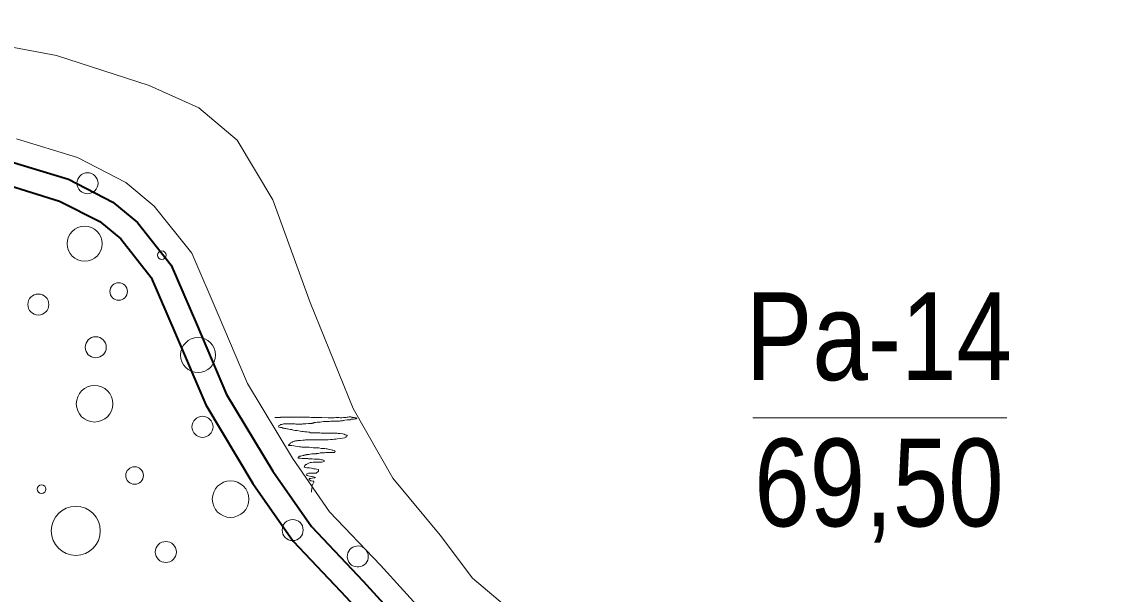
# Model space of a CAD drawing. Extents: x 640104 to 640970, y 6442278 to 6442689.
# Drawn here: x 640619.99 to 640656.92, y 6442622.5 to 6442642.09 of the extents above; entities that cross this region are included whole.
import ezdxf
from ezdxf.enums import TextEntityAlignment as Align

# ---------------------------------------------------------------- set-up
doc = ezdxf.new("R2010")
doc.units = 0
doc.header["$LTSCALE"] = 1.2
doc.linetypes.add('MEDIUM_DASHED', pattern=[4.5, 3, -1.5])
for name, color, linetype, lineweight in [('31', 7, 'Continuous', 13), ('32', 7, 'Continuous', 25), ('35', 7, 'Continuous', 35), ('40', 7, 'Continuous', 13), ('41', 7, 'Continuous', 13)]:
    doc.layers.add(name, color=color, linetype=linetype, lineweight=lineweight)

msp = doc.modelspace()

# ---------------------------------------------------------------- linework, layer by layer
at = {"layer": '31'}
for points in [[(640614.97, 6442642.09), (640621.18, 6442640.93), (640624.35, 6442639.91), (640626.05, 6442639.14), (640627.36, 6442638.03), (640628.58, 6442635.99), (640629.86, 6442632.49), (640631.33, 6442628.86), (640632.69, 6442626.48), (640634.3, 6442624.53), (640635.41, 6442623.06), (640637.17, 6442621.58), (640640.5, 6442618.88), (640642.64, 6442617.25), (640645.69, 6442615.13), (640647.73, 6442614.4), (640649.77, 6442613.94), (640651.6, 6442612.37), (640655.67, 6442609.41), (640658.72, 6442607.17)], [(640619.82, 6442638.08), (640621.9, 6442637.44), (640623.55, 6442636.59), (640624.53, 6442635.78), (640625.81, 6442634.17), (640626.71, 6442632.07), (640627.72, 6442629.71), (640629.25, 6442627.16), (640630.52, 6442625.33), (640632.26, 6442623.5), (640635.41, 6442620.04), (640639.01, 6442616.68), (640643.82, 6442612.84), (640649.81, 6442608.89), (640651.34, 6442607.83), (640657.57, 6442604.59)]]:
    msp.add_lwpolyline(points, dxfattribs=at)
at = {"layer": '32', "lineweight": 13}
msp.add_line((640645, 6442628.54), (640653.68, 6442628.54), dxfattribs=at)
at = {"layer": '35', "lineweight": 40}
msp.add_lwpolyline([(640619.6, 6442637.31), (640621.6, 6442636.7), (640623.11, 6442635.92), (640623.96, 6442635.22), (640625.11, 6442633.76), (640625.97, 6442631.76), (640627, 6442629.34), (640628.58, 6442626.72), (640629.9, 6442624.82), (640631.67, 6442622.96), (640634.84, 6442619.48), (640638.49, 6442616.08), (640643.35, 6442612.19), (640649.36, 6442608.23), (640650.93, 6442607.14), (640657.23, 6442603.87)], dxfattribs=at)
at = {"layer": '35', "linetype": 'MEDIUM_DASHED'}
msp.add_lwpolyline([(640619.39, 6442636.54), (640621.29, 6442635.95), (640622.67, 6442635.25), (640623.38, 6442634.66), (640624.42, 6442633.34), (640625.24, 6442631.44), (640626.29, 6442628.98), (640627.9, 6442626.29), (640629.28, 6442624.32), (640631.09, 6442622.41), (640634.27, 6442618.92), (640637.96, 6442615.47), (640642.88, 6442611.54), (640648.92, 6442607.56), (640650.51, 6442606.45), (640656.89, 6442603.14), (640661.89, 6442601.05)], dxfattribs=at)
at = {"layer": '40'}
for points in [[(640628.65, 6442628.55), (640628.69, 6442628.55), (640628.76, 6442628.55), (640628.84, 6442628.55), (640628.85, 6442628.56), (640628.92, 6442628.56), (640629.03, 6442628.56), (640629.24, 6442628.56), (640629.36, 6442628.56), (640629.39, 6442628.56), (640629.41, 6442628.56), (640629.46, 6442628.56), (640629.52, 6442628.56), (640629.59, 6442628.56), (640629.64, 6442628.56), (640629.68, 6442628.56), (640629.74, 6442628.56), (640629.79, 6442628.56), (640629.84, 6442628.56), (640629.89, 6442628.55), (640629.92, 6442628.55), (640629.97, 6442628.55), (640630.04, 6442628.55), (640630.26, 6442628.55), (640630.47, 6442628.54), (640630.53, 6442628.54), (640630.57, 6442628.54), (640630.6, 6442628.54), (640630.63, 6442628.54), (640630.68, 6442628.54), (640630.74, 6442628.55), (640630.77, 6442628.55), (640630.8, 6442628.55), (640630.81, 6442628.55), (640630.84, 6442628.55), (640630.88, 6442628.54), (640630.91, 6442628.54), (640630.94, 6442628.54), (640631, 6442628.55), (640631.04, 6442628.55), (640631.09, 6442628.55), (640631.12, 6442628.56), (640631.16, 6442628.56), (640631.19, 6442628.57), (640631.22, 6442628.57), (640631.25, 6442628.57), (640631.28, 6442628.56), (640631.3, 6442628.55), (640631.33, 6442628.55), (640631.36, 6442628.55)], [(640629.68, 6442628.34), (640629.65, 6442628.33), (640629.61, 6442628.33), (640629.59, 6442628.32), (640629.56, 6442628.32), (640629.54, 6442628.32), (640629.51, 6442628.32), (640629.48, 6442628.32), (640629.44, 6442628.32), (640629.4, 6442628.32), (640629.37, 6442628.32), (640629.33, 6442628.33), (640629.31, 6442628.33), (640629.28, 6442628.33), (640629.26, 6442628.33), (640629.23, 6442628.33), (640629.2, 6442628.33), (640629.15, 6442628.33), (640629.12, 6442628.33), (640629.1, 6442628.33), (640629.06, 6442628.33), (640629.04, 6442628.33), (640629, 6442628.33), (640628.98, 6442628.33), (640628.95, 6442628.33), (640628.92, 6442628.32), (640628.89, 6442628.31), (640628.86, 6442628.31), (640628.84, 6442628.3), (640628.82, 6442628.29), (640628.8, 6442628.28), (640628.79, 6442628.27), (640628.78, 6442628.24), (640628.79, 6442628.22), (640628.85, 6442628.21), (640628.89, 6442628.21), (640628.92, 6442628.19), (640628.95, 6442628.19), (640628.97, 6442628.19), (640628.99, 6442628.18), (640629.03, 6442628.18), (640629.06, 6442628.17), (640629.08, 6442628.16), (640629.13, 6442628.15), (640629.18, 6442628.14), (640629.23, 6442628.14), (640629.26, 6442628.13), (640629.29, 6442628.12), (640629.35, 6442628.11), (640629.42, 6442628.11)], [(640631.36, 6442628.55), (640631.39, 6442628.54), (640631.41, 6442628.54), (640631.44, 6442628.54), (640631.46, 6442628.52), (640631.44, 6442628.51), (640631.45, 6442628.52), (640631.43, 6442628.51), (640631.4, 6442628.51), (640631.36, 6442628.5), (640631.33, 6442628.5), (640631.3, 6442628.5), (640631.28, 6442628.49), (640631.25, 6442628.49), (640631.24, 6442628.47), (640631.2, 6442628.47), (640631.15, 6442628.47), (640631.12, 6442628.47), (640631.04, 6442628.46), (640631.01, 6442628.45), (640630.99, 6442628.45), (640630.96, 6442628.44), (640630.92, 6442628.44), (640630.9, 6442628.44), (640630.86, 6442628.43), (640630.84, 6442628.43), (640630.76, 6442628.43), (640630.72, 6442628.43), (640630.68, 6442628.43), (640630.62, 6442628.43), (640630.58, 6442628.43), (640630.55, 6442628.43), (640630.51, 6442628.42), (640630.47, 6442628.42), (640630.36, 6442628.42), (640630.33, 6442628.42), (640630.31, 6442628.41), (640630.26, 6442628.4), (640630.2, 6442628.39), (640630.14, 6442628.39), (640630.1, 6442628.39), (640630.04, 6442628.38), (640630, 6442628.38), (640629.97, 6442628.36), (640629.93, 6442628.36), (640629.92, 6442628.35), (640629.89, 6442628.35), (640629.85, 6442628.35), (640629.82, 6442628.35), (640629.8, 6442628.35), (640629.71, 6442628.34), (640629.68, 6442628.34)], [(640629.42, 6442628.11), (640629.52, 6442628.09), (640629.58, 6442628.07), (640629.62, 6442628.07), (640629.68, 6442628.06), (640629.75, 6442628.06), (640629.8, 6442628.05), (640629.84, 6442628.05), (640629.87, 6442628.03), (640629.92, 6442628.03), (640629.96, 6442628.03), (640630.02, 6442628.03), (640630.08, 6442628.03), (640630.12, 6442628.03), (640630.19, 6442628.03), (640630.24, 6442628.02), (640630.28, 6442628.02), (640630.31, 6442628.02), (640630.36, 6442628.02), (640630.4, 6442628.02), (640630.46, 6442628.02), (640630.52, 6442628.02), (640630.58, 6442628.02), (640630.62, 6442628.02), (640630.68, 6442628.02), (640630.7, 6442628.02), (640630.74, 6442628.02), (640630.78, 6442628.02), (640630.82, 6442628.01), (640630.86, 6442628.01), (640630.89, 6442628), (640630.98, 6442627.99), (640631.02, 6442627.98), (640631.06, 6442627.96), (640631.09, 6442627.95), (640631.12, 6442627.95), (640631.12, 6442627.92), (640631.11, 6442627.9), (640631.09, 6442627.89), (640631.08, 6442627.88), (640631.06, 6442627.87), (640631.03, 6442627.86), (640630.97, 6442627.84), (640630.88, 6442627.83), (640630.79, 6442627.82), (640630.74, 6442627.81), (640630.68, 6442627.81), (640630.62, 6442627.8), (640630.56, 6442627.8), (640630.47, 6442627.79), (640630.34, 6442627.79), (640630.23, 6442627.79)], [(640630.23, 6442627.79), (640630.17, 6442627.79), (640630.12, 6442627.79), (640630.07, 6442627.79), (640630.03, 6442627.79), (640629.99, 6442627.79), (640629.93, 6442627.79), (640629.88, 6442627.79), (640629.76, 6442627.79), (640629.7, 6442627.79), (640629.67, 6442627.78), (640629.61, 6442627.78), (640629.53, 6442627.76), (640629.44, 6442627.76), (640629.41, 6442627.75), (640629.37, 6442627.75), (640629.36, 6442627.75), (640629.33, 6442627.74), (640629.31, 6442627.74), (640629.28, 6442627.73), (640629.26, 6442627.72), (640629.24, 6442627.71), (640629.2, 6442627.68), (640629.18, 6442627.67), (640629.17, 6442627.65), (640629.15, 6442627.64), (640629.14, 6442627.63), (640629.12, 6442627.61), (640629.12, 6442627.59), (640629.13, 6442627.59), (640629.16, 6442627.59), (640629.2, 6442627.59), (640629.23, 6442627.59), (640629.3, 6442627.58), (640629.36, 6442627.57), (640629.42, 6442627.56), (640629.5, 6442627.55), (640629.54, 6442627.55), (640629.58, 6442627.54), (640629.62, 6442627.54), (640629.73, 6442627.54), (640629.82, 6442627.54), (640629.89, 6442627.53), (640629.96, 6442627.52), (640630.06, 6442627.51), (640630.16, 6442627.51), (640630.24, 6442627.49), (640630.29, 6442627.49), (640630.36, 6442627.49), (640630.41, 6442627.48)], [(640630.41, 6442627.48), (640630.44, 6442627.48), (640630.48, 6442627.47), (640630.53, 6442627.46), (640630.58, 6442627.45), (640630.61, 6442627.43), (640630.64, 6442627.43), (640630.68, 6442627.42), (640630.7, 6442627.41), (640630.71, 6442627.38), (640630.69, 6442627.37), (640630.68, 6442627.36), (640630.65, 6442627.35), (640630.57, 6442627.35), (640630.53, 6442627.35), (640630.51, 6442627.35), (640630.46, 6442627.35), (640630.4, 6442627.35), (640630.35, 6442627.34), (640630.32, 6442627.34), (640630.28, 6442627.34), (640630.2, 6442627.34), (640630.15, 6442627.32), (640630.12, 6442627.32), (640630.08, 6442627.32), (640630.06, 6442627.31), (640630.02, 6442627.31), (640629.96, 6442627.31), (640629.92, 6442627.31), (640629.86, 6442627.3), (640629.82, 6442627.29), (640629.8, 6442627.29), (640629.76, 6442627.29), (640629.74, 6442627.28), (640629.7, 6442627.28), (640629.69, 6442627.27), (640629.65, 6442627.26), (640629.64, 6442627.25), (640629.61, 6442627.25), (640629.58, 6442627.24), (640629.54, 6442627.23), (640629.5, 6442627.23), (640629.47, 6442627.21), (640629.45, 6442627.19), (640629.45, 6442627.16), (640629.48, 6442627.16), (640629.52, 6442627.16), (640629.59, 6442627.15), (640629.64, 6442627.15), (640629.68, 6442627.15), (640629.74, 6442627.15), (640629.78, 6442627.15)], [(640629.78, 6442627.15), (640629.8, 6442627.14), (640629.82, 6442627.14), (640629.86, 6442627.14), (640629.91, 6442627.14), (640629.93, 6442627.14), (640630, 6442627.13), (640630.06, 6442627.13), (640630.08, 6442627.13), (640630.12, 6442627.13), (640630.14, 6442627.13), (640630.18, 6442627.13), (640630.22, 6442627.12), (640630.25, 6442627.11), (640630.28, 6442627.1), (640630.32, 6442627.09), (640630.34, 6442627.08), (640630.34, 6442627.05), (640630.26, 6442627.03), (640630.16, 6442627.03), (640630.12, 6442627.03), (640630.04, 6442627.02), (640630, 6442627.02), (640629.96, 6442627.02), (640629.91, 6442627.01), (640629.86, 6442627.01), (640629.81, 6442626.99), (640629.76, 6442626.97), (640629.74, 6442626.95), (640629.71, 6442626.94), (640629.69, 6442626.92), (640629.68, 6442626.91), (640629.67, 6442626.88), (640629.65, 6442626.86), (640629.67, 6442626.85), (640629.7, 6442626.84), (640629.75, 6442626.83), (640629.84, 6442626.83), (640629.91, 6442626.82), (640629.95, 6442626.81), (640629.98, 6442626.8), (640630.03, 6442626.8), (640630.08, 6442626.79), (640630.15, 6442626.77), (640630.15, 6442626.74), (640630.14, 6442626.71), (640630.13, 6442626.7), (640630.08, 6442626.66), (640630.06, 6442626.65), (640630.02, 6442626.65), (640629.96, 6442626.65), (640629.91, 6442626.65), (640629.86, 6442626.65), (640629.8, 6442626.65), (640629.75, 6442626.63), (640629.74, 6442626.61), (640629.73, 6442626.59), (640629.74, 6442626.58), (640629.76, 6442626.57), (640629.84, 6442626.55), (640629.9, 6442626.54), (640629.93, 6442626.53), (640629.97, 6442626.52), (640630.01, 6442626.51), (640630.04, 6442626.5), (640630.02, 6442626.49), (640629.98, 6442626.49), (640629.93, 6442626.48), (640629.87, 6442626.47), (640629.84, 6442626.47), (640629.82, 6442626.47), (640629.82, 6442626.43), (640629.84, 6442626.42), (640629.85, 6442626.41), (640629.88, 6442626.39), (640629.91, 6442626.39), (640629.95, 6442626.38), (640629.98, 6442626.37), (640629.99, 6442626.34), (640629.97, 6442626.32), (640629.96, 6442626.3), (640629.95, 6442626.27), (640629.93, 6442626.26), (640629.93, 6442626.23), (640629.93, 6442626.19), (640629.93, 6442626.17), (640629.92, 6442626.15), (640629.92, 6442626.11), (640629.92, 6442626.1), (640629.91, 6442626.07), (640629.9, 6442626.04), (640629.9, 6442626.01), (640629.9, 6442626), (640629.9, 6442626.03)]]:
    msp.add_lwpolyline(points, dxfattribs=at)
at = {"layer": '41'}
for centre, radius in [((640622.244, 6442636.563), 0.36), ((640622.148, 6442634.493), 0.6), ((640624.785, 6442634.103), 0.15), ((640623.312, 6442632.861), 0.3), ((640620.563, 6442632.415), 0.36), ((640622.527, 6442630.954), 0.36), ((640626.027, 6442630.686), 0.6), ((640622.486, 6442629.021), 0.624), ((640626.178, 6442628.233), 0.36), ((640623.855, 6442626.567), 0.3), ((640627.137, 6442625.76), 0.624), ((640620.675, 6442626.102), 0.15), ((640621.845, 6442624.674), 0.838), ((640629.261, 6442624.703), 0.36), ((640624.924, 6442623.952), 0.36)]:
    msp.add_circle(centre, radius, dxfattribs=at)
msp.add_arc((640631.488, 6442623.8), 0.36, 54.1657, 32.8357, dxfattribs=at)

# ---------------------------------------------------------------- texts
at = {"layer": '32', "width": 0.85}
for s, p in [('Pa-14', (640649.31, 6442629.83)), ('69,50', (640649.31, 6442624.83))]:
    msp.add_text(s, height=3, dxfattribs=at).set_placement(p, align=Align.CENTER)

doc.saveas('drawing.dxf')
